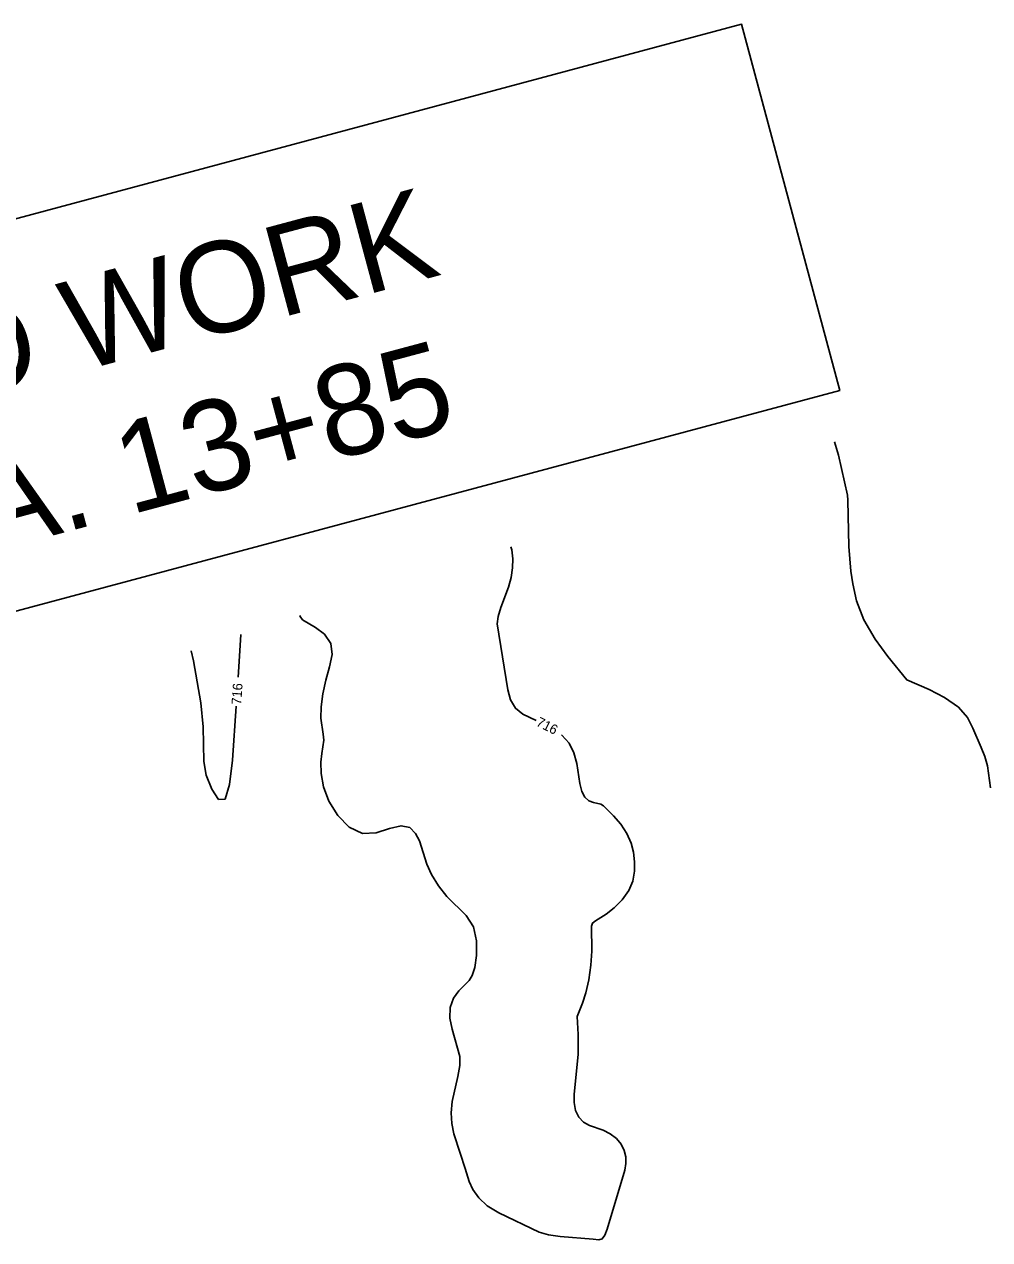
# Model space of a CAD drawing. Extents: x -361782338 to 28259792, y -263199453 to 8342113.
# Drawn here: x 1404261 to 1404659, y 576969 to 577471 of the extents above; entities that cross this region are included whole.
import ezdxf

# ---------------------------------------------------------------- set-up
doc = ezdxf.new("R2010")
doc.units = 0
for name, color, linetype in [('DT_X_Contour_Minor', 7, 'Continuous'), ('Level 19', 7, 'Continuous'), ('Level 40', 7, 'Continuous')]:
    doc.layers.add(name, color=color, linetype=linetype)

msp = doc.modelspace()

# ---------------------------------------------------------------- linework, layer by layer
at = {"layer": 'DT_X_Contour_Minor'}
for points in [[(1404595.39, 577298.26), (1404597, 577292.65), (1404600.65, 577276.15), (1404600.78, 577274.14), (1404601.31, 577255.03), (1404602.14, 577244.75), (1404602.86, 577239.5), (1404604.46, 577232.58), (1404607.48, 577224.73), (1404612.11, 577216.74), (1404617.28, 577209.56), (1404625.17, 577199.94), (1404634.47, 577195.86), (1404640.79, 577192.58), (1404646.47, 577188.65), (1404650.22, 577184.34), (1404652.49, 577179.94), (1404655.82, 577171.94), (1404657.4, 577168.26), (1404658.54, 577164.34), (1404659.77, 577155.24)], [(1404472.14, 577183.14), (1404466.67, 577185.67), (1404463.6, 577188.17), (1404461.66, 577191.58), (1404460.53, 577195.84), (1404456.13, 577222.99), (1404456.52, 577226.11), (1404457.67, 577229.81), (1404460.75, 577238.15), (1404461.83, 577242.22), (1404462.43, 577246.11), (1404462.54, 577249.88), (1404462.18, 577253.53), (1404461.8, 577254.81)], [(1404374.69, 577226.47), (1404374.8, 577226.11), (1404375.76, 577224.7), (1404381.06, 577221.58), (1404384.79, 577218.71), (1404387.42, 577214.97), (1404387.94, 577210.43), (1404386.93, 577205.29), (1404385.39, 577199.77), (1404384.17, 577194.14), (1404383.46, 577188.78), (1404383.32, 577184.12), (1404384.22, 577177.53), (1404384.5, 577174.99), (1404383.7, 577169.51), (1404383.3, 577165.84), (1404383.43, 577161.17), (1404384.43, 577155.71), (1404386.64, 577149.79), (1404390.26, 577143.88), (1404395, 577139.02), (1404400.46, 577136.41), (1404406.21, 577136.7), (1404411.72, 577138.45), (1404416.45, 577139.67), (1404420, 577138.86), (1404422.44, 577136.46), (1404424.01, 577133.41), (1404427, 577123.73), (1404429, 577119.46), (1404431.82, 577114.85), (1404435.37, 577110.43), (1404443.35, 577102.54), (1404446.26, 577097.87), (1404447.56, 577092.1), (1404447.58, 577086.1), (1404446.86, 577081.06), (1404445.84, 577077.8), (1404444.47, 577075.74), (1404440.28, 577071.54), (1404438.04, 577068.45), (1404436.64, 577064.64), (1404436.58, 577060.2), (1404437.5, 577055.59), (1404440.75, 577044.41), (1404440.75, 577040.66), (1404439.89, 577036.06), (1404437.53, 577025.78), (1404437.1, 577021.04), (1404437.34, 577016.66), (1404438.16, 577012.46), (1404440.81, 577004.44), (1404442.85, 576998.11), (1404444.49, 576992.67), (1404446.05, 576989.42), (1404448.48, 576985.96), (1404452.03, 576982.67), (1404456.74, 576979.82), (1404473.47, 576971.78), (1404477.24, 576970.65), (1404482.16, 576970.02), (1404495.77, 576968.95), (1404498.01, 576968.7), (1404499.47, 576969.1), (1404500.54, 576970.52), (1404501.51, 576973.04), (1404508.82, 576997.48), (1404509.18, 577000.17), (1404509.14, 577002.89), (1404508.58, 577005.59), (1404507.33, 577008.17), (1404505.34, 577010.48), (1404502.78, 577012.43), (1404499.9, 577013.92), (1404494.14, 577015.86), (1404491.69, 577017.19), (1404489.77, 577019.31), (1404488.47, 577022.08), (1404487.82, 577025.29), (1404487.83, 577028.74), (1404489.49, 577045.16), (1404489.51, 577053.4), (1404489.1, 577060.89), (1404491.26, 577066.33), (1404492.7, 577070.69), (1404493.97, 577076.05), (1404494.77, 577082.02), (1404495.12, 577087.87), (1404495.06, 577098.22), (1404495.51, 577099.48), (1404496.63, 577100.4), (1404501.12, 577103.11), (1404504.37, 577105.7), (1404507.69, 577109.06), (1404510.43, 577112.86), (1404512.06, 577116.83), (1404512.75, 577120.84), (1404512.78, 577124.81), (1404512.38, 577128.68), (1404511.42, 577132.51), (1404509.68, 577136.38)], [(1404349.21, 577200.96), (1404350.35, 577218.51), (1404350.35, 577218.56)], [(1404329.83, 577211.88), (1404330.76, 577207.71), (1404333.73, 577190.4), (1404334.72, 577180.54), (1404334.95, 577166.14), (1404336.01, 577160.58), (1404338.26, 577154.69), (1404341.11, 577150.54), (1404343.77, 577150.65), (1404345.62, 577156.68), (1404346.79, 577166.77), (1404348.37, 577188.99)], [(1404509.68, 577136.38), (1404507.07, 577140.27), (1404504.16, 577143.8), (1404499.97, 577147.93), (1404498.82, 577148.55), (1404495.88, 577149.18), (1404493.94, 577149.97), (1404492.22, 577151.46), (1404491.04, 577153.85), (1404490.28, 577157.06), (1404488.96, 577165.3), (1404487.79, 577169.72), (1404485.83, 577173.76), (1404482.85, 577177.08), (1404482.6, 577177.26)]]:
    msp.add_lwpolyline(points, dxfattribs=at)
at = {"layer": 'Level 40'}
msp.add_lwpolyline([(1404095.56, 577346.98), (1404556.97, 577470.62), (1404597.48, 577319.44), (1404136.07, 577195.81)], close=True, dxfattribs=at)

# ---------------------------------------------------------------- texts
at = {"layer": 'Level 19'}
for rotation, p in [(85.9379, (1404350.41, 577189.49)), (333.0088, (1404471.86, 577181.17))]:
    msp.add_text('716', height=4, rotation=rotation, dxfattribs=at).set_placement(p)
at = {"layer": 'Level 40'}
for s, p in [('END WORK', (1404167.28, 577295.93)), ('STA. 13+85', (1404183.46, 577235.56))]:
    msp.add_text(s, height=37.5, rotation=15, dxfattribs=at).set_placement(p)

doc.saveas('drawing.dxf')
